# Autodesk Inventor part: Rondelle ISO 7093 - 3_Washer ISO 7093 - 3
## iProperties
Created: 2011-01
Part Number: Rondelle ISO 7093 - 3_Washer ISO 7093 - 3
Document SubType Name: Modeling
Designer: eric
Density: 1 g/cm^3
Mass: 0.0243536 g
Surface Area: 0.865195 cm^2
Volume: 0.0243536 cm^3
Author: eric
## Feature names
1. Base1
